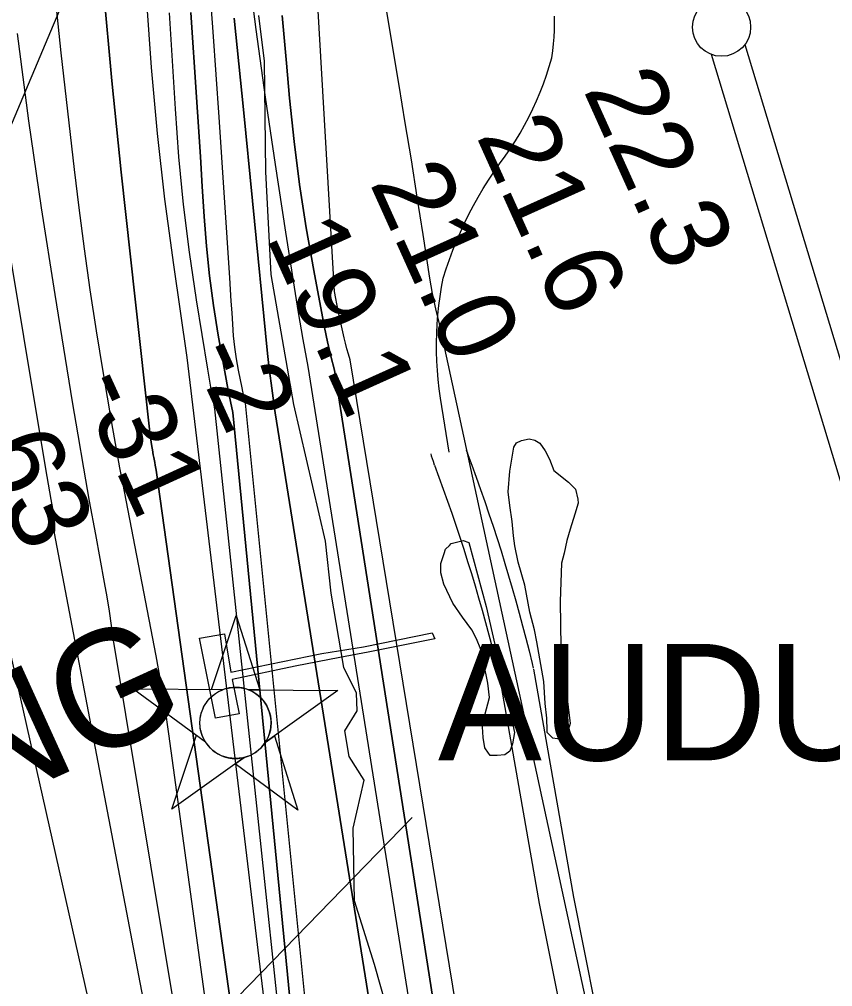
# Model space of a CAD drawing. Extents: x 3651524 to 3689615, y 505651 to 531377.
# Drawn here: x 3660133 to 3660831, y 518426 to 519257 of the extents above; entities that cross this region are included whole.
import ezdxf

# ---------------------------------------------------------------- set-up
doc = ezdxf.new("R2010")
doc.units = 0
for name, color, linetype in [('V-CHAN-DOCK', 7, 'Continuous'), ('V-CHAN-NAID', 7, 'Continuous'), ('V-RIVR-EDGE', 7, 'Continuous'), ('V-RIVR-RANG', 7, 'Continuous'), ('V-ROAD-CNTR', 7, 'Continuous'), ('V-SITE-VEGE', 7, 'Continuous'), ('V-SURV-LINE', 7, 'Continuous'), ('V-TOPO-DPTH', 7, 'Continuous'), ('V-TOPO-MAJR', 7, 'Continuous'), ('V-TOPO-MINR', 7, 'Continuous'), ('V-TOPO-WATR', 7, 'Continuous'), ('V-UTIL-LINE', 7, 'Continuous')]:
    doc.layers.add(name, color=color, linetype=linetype)

msp = doc.modelspace()

# ---------------------------------------------------------------- linework, layer by layer
at = {"layer": 'V-CHAN-DOCK'}
msp.add_lwpolyline([(3660489.731, 518724.865), (3660432.523, 518713.406), (3660408.098, 518709.087), (3660369.958, 518701.446), (3660315.717, 518689.934), (3660321.732, 518660.732), (3660301.475, 518656.933), (3660287.84, 518725.463), (3660309.284, 518729.242), (3660314.644, 518696.488), (3660392.716, 518712.327), (3660428.449, 518718.229), (3660487.452, 518730.249), (3660489.731, 518724.865)], dxfattribs=at)
at = {"layer": 'V-CHAN-NAID'}
for points in [[(3660307.778, 518681.337), (3660298.191, 518681.405), (3660319.317, 518744.889), (3660339.541, 518681.112), (3660329.954, 518681.18), (3660328.377, 518681.758), (3660326.282, 518682.378), (3660324.242, 518682.829), (3660322.206, 518683.137), (3660321.039, 518683.251), (3660319.505, 518683.332), (3660317.783, 518683.33), (3660316.413, 518683.26), (3660314.507, 518683.059), (3660313.141, 518682.84), (3660311.357, 518682.456), (3660309.827, 518682.036), (3660308.795, 518681.705)], [(3660307.778, 518681.337), (3660231.287, 518681.879), (3660292.852, 518636.48), (3660291.739, 518638.389), (3660290.929, 518640.017), (3660290.104, 518641.985), (3660289.408, 518644.039), (3660289.043, 518645.362), (3660288.682, 518646.988), (3660288.438, 518648.433), (3660288.25, 518650.031), (3660288.141, 518651.767), (3660288.129, 518653.348), (3660288.236, 518655.422), (3660288.419, 518657.04), (3660288.811, 518659.243), (3660289.292, 518661.166), (3660289.895, 518663.053), (3660290.55, 518664.732), (3660291.277, 518666.32), (3660292.091, 518667.855), (3660293.152, 518669.592), (3660294.183, 518671.062), (3660295.183, 518672.331), (3660296.185, 518673.477), (3660297.494, 518674.814), (3660298.545, 518675.779), (3660300.262, 518677.176), (3660301.474, 518678.046), (3660303.161, 518679.116), (3660304.892, 518680.061), (3660306.338, 518680.745)], [(3660329.954, 518681.18), (3660406.446, 518680.637), (3660344.243, 518636.115), (3660345.154, 518637.604), (3660346.132, 518639.451), (3660346.847, 518641.036), (3660347.586, 518642.991), (3660348.131, 518644.776), (3660348.529, 518646.415), (3660348.89, 518648.425), (3660349.076, 518649.998), (3660349.2, 518652.204), (3660349.17, 518654.266), (3660348.982, 518656.486), (3660348.716, 518658.244), (3660348.225, 518660.476), (3660347.585, 518662.616), (3660346.835, 518664.598), (3660346.187, 518666.041), (3660345.18, 518667.957), (3660344.118, 518669.679), (3660342.904, 518671.381), (3660341.643, 518672.92), (3660340.371, 518674.286), (3660338.739, 518675.818), (3660336.996, 518677.23), (3660335.313, 518678.407), (3660333.426, 518679.539), (3660331.954, 518680.3)], [(3660326.212, 518623.209), (3660264.009, 518578.687), (3660285.135, 518642.17), (3660292.852, 518636.48), (3660293.487, 518635.516), (3660294.87, 518633.657), (3660296.083, 518632.241), (3660297.549, 518630.738), (3660298.938, 518629.487), (3660300.392, 518628.331), (3660301.795, 518627.344), (3660303.473, 518626.308), (3660305.187, 518625.397), (3660306.978, 518624.586), (3660308.424, 518624.03), (3660310.052, 518623.501), (3660312.278, 518622.937), (3660313.81, 518622.65), (3660315.835, 518622.393), (3660317.372, 518622.289), (3660319.233, 518622.267), (3660320.922, 518622.345), (3660322.632, 518622.521), (3660324.534, 518622.832)], [(3660344.243, 518636.115), (3660352.039, 518641.696), (3660372.263, 518577.919), (3660318.415, 518617.629), (3660326.212, 518623.209), (3660327.878, 518623.685), (3660329.49, 518624.245), (3660331.648, 518625.159), (3660333.383, 518626.043), (3660335.249, 518627.157), (3660336.988, 518628.369), (3660338.54, 518629.614), (3660339.827, 518630.782), (3660341.211, 518632.202), (3660342.415, 518633.604), (3660343.534, 518635.076)]]:
    msp.add_lwpolyline(points, close=True, dxfattribs=at)
msp.add_circle((3660318.664, 518652.802), 30.541, dxfattribs=at)
at = {"layer": 'V-RIVR-EDGE'}
msp.add_lwpolyline([(3660449.43, 518405.026), (3660437.888, 518445.494), (3660420.867, 518500.069), (3660419.796, 518562.57), (3660429.088, 518603.6), (3660416.271, 518623.851), (3660412.649, 518645.919), (3660423.108, 518663.049), (3660422.533, 518678.369), (3660411.558, 518700.454), (3660400.687, 518764.205), (3660395.896, 518808.945), (3660368.613, 518926.044), (3660349.281, 519037.608), (3660344.598, 519125.852), (3660343.607, 519220.827), (3660338.802, 519260.054)], dxfattribs=at)
at = {"layer": 'V-ROAD-CNTR'}
for points in [[(3660501.976, 518885.126), (3660494.673, 518931.668), (3660493.578, 518939.553), (3660492.693, 518947.464), (3660492.021, 518955.396), (3660491.562, 518963.344), (3660491.319, 518971.303), (3660491.288, 518979.263), (3660491.47, 518987.222), (3660491.868, 518995.172), (3660492.476, 519003.11), (3660493.299, 519011.03), (3660494.333, 519018.923), (3660495.581, 519026.785), (3660497.037, 519034.613), (3660499.576, 519042.657), (3660502.321, 519050.636), (3660505.263, 519058.544), (3660508.405, 519066.375), (3660511.745, 519074.123), (3660515.278, 519081.784), (3660519.004, 519089.354), (3660522.919, 519096.827), (3660527.023, 519104.198), (3660531.312, 519111.462), (3660535.783, 519118.613), (3660540.434, 519125.652), (3660545.259, 519132.571), (3660550.258, 519139.364), (3660554.684, 519145.801), (3660558.921, 519152.362), (3660562.964, 519159.047), (3660566.81, 519165.846), (3660570.455, 519172.756), (3660573.896, 519179.771), (3660577.134, 519186.882), (3660580.161, 519194.082), (3660582.975, 519201.371), (3660585.576, 519208.738), (3660587.962, 519216.178), (3660590.126, 519223.684), (3660591.042, 519229.603), (3660591.751, 519235.55), (3660592.252, 519241.518), (3660592.545, 519247.502), (3660592.631, 519253.491), (3660592.508, 519259.479)], [(3660486.267, 518883.729), (3660486.749, 518882.172), (3660488.276, 518877.522), (3660489.339, 518874.431)], [(3660516.738, 518887.006), (3660517.707, 518884.193)], [(3660517.576, 518884.558), (3660521.452, 518874.176), (3660525.27, 518863.714), (3660529.013, 518853.226), (3660532.68, 518842.711), (3660536.27, 518832.17), (3660539.784, 518821.602), (3660543.221, 518811.009), (3660546.58, 518800.392), (3660549.863, 518789.751), (3660553.069, 518779.086), (3660556.197, 518768.399), (3660559.248, 518757.687), (3660562.22, 518746.956), (3660565.115, 518736.204), (3660567.932, 518725.429), (3660570.671, 518714.635), (3660573.327, 518703.837), (3660574.289, 518699.841)], [(3660489.47, 518874.066), (3660493.308, 518863.786), (3660497.052, 518853.53), (3660500.721, 518843.246), (3660504.316, 518832.937), (3660507.836, 518822.6), (3660511.282, 518812.24), (3660514.651, 518801.855), (3660517.946, 518791.444), (3660521.165, 518781.011), (3660524.307, 518770.554), (3660527.375, 518760.075), (3660530.366, 518749.575), (3660533.28, 518739.052), (3660536.119, 518728.51), (3660538.88, 518717.947), (3660541.565, 518707.363), (3660544.177, 518696.745), (3660545.121, 518692.821)], [(3660544.93, 518693.741), (3660579.298, 518497.685), (3660612.46, 518331.561)], [(3660574.48, 518698.921), (3660608.786, 518503.213), (3660636.628, 518363.743)]]:
    msp.add_lwpolyline(points, dxfattribs=at)
at = {"layer": 'V-SITE-VEGE'}
for points in [[(3660557.688, 518889.393), (3660559.91, 518893.129), (3660564.262, 518895.209), (3660570.761, 518896.713), (3660575.594, 518895.547), (3660579.86, 518892.776), (3660584.597, 518886.221), (3660588.246, 518879.147), (3660591.849, 518869.376), (3660604.616, 518859.441), (3660610.443, 518853.408), (3660612.446, 518844.743), (3660612.929, 518841.499), (3660610.062, 518831.842), (3660606.058, 518818.971), (3660603.191, 518809.314), (3660600.844, 518798.568), (3660598.536, 518789.981), (3660597.415, 518757.105), (3660597.798, 518717.73), (3660605.81, 518652.333), (3660604.069, 518645.353), (3660604.03, 518643.199), (3660600.758, 518641.098), (3660596.426, 518640.096), (3660594.79, 518639.048), (3660591.026, 518639.654), (3660586.258, 518644.59), (3660586.286, 518646.207), (3660585.938, 518657), (3660584.54, 518669.428), (3660583.255, 518688.327), (3660577.388, 518722.405), (3660575.412, 518732.686), (3660571.365, 518747.858), (3660566.923, 518771.125), (3660561.336, 518790.639), (3660558.35, 518804.712), (3660557.424, 518813.357), (3660556.025, 518825.786), (3660554.106, 518839.303), (3660552.699, 518851.192), (3660554.092, 518868.964)], [(3660502.271, 518805.167), (3660503.918, 518806.754), (3660514.207, 518809.267), (3660519.03, 518807.565), (3660533.702, 518752.839), (3660550.727, 518678.654), (3660558.215, 518644.547), (3660556.427, 518634.872), (3660554.155, 518628.439), (3660549.785, 518625.281), (3660543.305, 518624.855), (3660537.376, 518624.962), (3660533.157, 518630.43), (3660532.637, 518631.515), (3660531.173, 518640.172), (3660530.796, 518649.345), (3660532.594, 518659.56), (3660536.635, 518674.589), (3660535.238, 518687.018), (3660531.758, 518703.797), (3660529.274, 518715.702), (3660525.66, 518724.937), (3660521.482, 518732.561), (3660513.585, 518743.485), (3660505.167, 518755.499), (3660497.366, 518771.815), (3660494.843, 518781.568), (3660494.987, 518789.653), (3660497.833, 518798.233), (3660498.978, 518801.987)]]:
    msp.add_lwpolyline(points, close=True, dxfattribs=at)
at = {"layer": 'V-SURV-LINE'}
for points in [[(3660756.034, 519235.203), (3660876.692, 518836.198)], [(3660847.983, 518827.494), (3660727.324, 519226.499)]]:
    msp.add_lwpolyline(points, dxfattribs=at)
msp.add_circle((3660735.893, 519249.984), 25, dxfattribs=at)
at = {"layer": 'V-TOPO-DPTH'}
for points in [[(3660205.241, 519282.629), (3660212.412, 519204.024), (3660220.442, 519125.491), (3660244.815, 518904.975), (3660245.253, 518901.266), (3660245.727, 518897.561), (3660246.256, 518893.864), (3660246.821, 518890.171), (3660247.303, 518887.17), (3660248.058, 518882.803), (3660248.477, 518880.628), (3660249.369, 518876.287), (3660249.815, 518874.116), (3660250.687, 518869.77), (3660367.592, 518031.054)], [(3660205.241, 519282.629), (3660212.412, 519204.024), (3660220.442, 519125.491), (3660244.815, 518904.975), (3660245.253, 518901.266), (3660245.727, 518897.561), (3660246.256, 518893.864), (3660246.821, 518890.171), (3660247.303, 518887.17), (3660248.058, 518882.803), (3660248.477, 518880.628), (3660249.369, 518876.287), (3660249.815, 518874.116), (3660250.687, 518869.77), (3660367.592, 518031.054)], [(3660344.498, 518038.702), (3660261.495, 518643.52), (3660258.216, 518665.89), (3660254.475, 518688.188), (3660250.427, 518710.437), (3660221.838, 518858.822), (3660219.404, 518871.676), (3660217.024, 518884.541), (3660214.726, 518897.42), (3660212.483, 518910.309), (3660204.945, 518954.448), (3660199.234, 518989.451), (3660193.87, 519024.506), (3660189.025, 519059.635), (3660184.527, 519094.816), (3660180.549, 519127.872), (3660174.692, 519177.914), (3660169.05, 519227.979), (3660163.731, 519278.08)], [(3660344.498, 518038.702), (3660261.495, 518643.52), (3660258.216, 518665.89), (3660254.475, 518688.188), (3660250.427, 518710.437), (3660221.838, 518858.822), (3660219.404, 518871.676), (3660217.024, 518884.541), (3660214.726, 518897.42), (3660212.483, 518910.309), (3660204.945, 518954.448), (3660199.234, 518989.451), (3660193.87, 519024.506), (3660189.025, 519059.635), (3660184.527, 519094.816), (3660180.549, 519127.872), (3660174.692, 519177.914), (3660169.05, 519227.979), (3660163.731, 519278.08)], [(3660391.13, 518016.01), (3660277.155, 518966.485), (3660265.579, 519046.022), (3660258.116, 519102.367), (3660251.62, 519158.81), (3660246.575, 519215.402), (3660242.497, 519272.092)], [(3660391.13, 518016.01), (3660277.155, 518966.485), (3660265.579, 519046.022), (3660258.116, 519102.367), (3660251.62, 519158.81), (3660246.575, 519215.402), (3660242.497, 519272.092)], [(3660280.448, 519262.481), (3660285.21, 519190.002), (3660286.87, 519164.386), (3660288.5, 519138.768), (3660290.086, 519113.147), (3660291.642, 519087.524), (3660293.628, 519061.954), (3660296.217, 519036.456), (3660299.709, 519011.066), (3660303.803, 518985.748), (3660310.649, 518947.717), (3660312.456, 518938.168), (3660314.378, 518928.643), (3660316.471, 518919.154), (3660403.946, 518019.13)], [(3660403.946, 518019.13), (3660316.471, 518919.154), (3660314.378, 518928.643), (3660312.456, 518938.168), (3660310.649, 518947.717), (3660303.803, 518985.748), (3660299.709, 519011.066), (3660296.217, 519036.456), (3660293.628, 519061.954), (3660291.642, 519087.524), (3660290.086, 519113.147), (3660288.5, 519138.768), (3660286.87, 519164.386), (3660285.21, 519190.002), (3660280.448, 519262.481)], [(3660317.62, 519257.742), (3660325.565, 519179.395), (3660333.363, 519101.034), (3660346.224, 518969.939), (3660347.601, 518957.129), (3660349.136, 518944.339), (3660350.908, 518931.58), (3660352.838, 518918.842), (3660486.821, 518079.665)], [(3660486.821, 518079.665), (3660352.838, 518918.842), (3660350.908, 518931.58), (3660349.136, 518944.339), (3660347.601, 518957.129), (3660346.224, 518969.939), (3660333.363, 519101.034), (3660325.565, 519179.395), (3660317.62, 519257.742)], [(3660358.831, 519259.972), (3660362.302, 519219.012), (3660364.983, 519189.115), (3660368.883, 519151.905), (3660373.527, 519114.8), (3660379.284, 519077.852), (3660385.785, 519041.007), (3660395.145, 518992.252), (3660397.713, 518979.91), (3660400.536, 518967.632), (3660403.738, 518955.446), (3660519.463, 518215.358)]]:
    msp.add_lwpolyline(points, dxfattribs=at)
at = {"layer": 'V-TOPO-MAJR'}
msp.add_lwpolyline([(3660331.859, 518013.486), (3660213.803, 518723.901), (3660212.199, 518736.334), (3660210.434, 518748.743), (3660208.427, 518761.114), (3660206.26, 518773.462), (3660198.621, 518814.619), (3660193.439, 518843.052), (3660188.379, 518871.507), (3660183.504, 518899.993), (3660178.751, 518928.501), (3660163.729, 519020.428), (3660152.119, 519094.993), (3660141.259, 519169.661), (3660131.524, 519244.484)], dxfattribs=at)
at = {"layer": 'V-TOPO-MINR'}
for points in [[(3660417.121, 518964.584), (3660415.625, 518969.239), (3660414.239, 518973.925), (3660413.016, 518978.657), (3660411.904, 518983.418), (3660406.917, 519006.569), (3660403.764, 519022.981), (3660369.467, 519608.342), (3660368.446, 519618.497), (3660367.5, 519628.659), (3660366.667, 519638.83), (3660365.907, 519649.008), (3660360.294, 519730.297), (3660357.146, 519781.141), (3660354.483, 519832.006), (3660352.544, 519882.905), (3660351.089, 519933.825), (3660340.334, 520435.426)], [(3660806.665, 517551.768), (3660493.857, 518995.4), (3660490.531, 519008.344), (3660487.797, 519021.426), (3660485.457, 519034.6), (3660479.674, 519072.1), (3660474.682, 519104.084), (3660469.612, 519136.055), (3660464.424, 519168.007), (3660459.159, 519199.947), (3660387.172, 519631.683)], [(3660418.729, 518011.665), (3660327.319, 518927.2), (3660326.486, 518930.505), (3660325.694, 518933.819), (3660324.964, 518937.147), (3660324.275, 518940.485), (3660321.304, 518955.602), (3660319.583, 518965.391), (3660318.126, 518975.214), (3660317.065, 518985.087), (3660316.267, 518994.994), (3660315.66, 519004.926), (3660315.041, 519014.857), (3660314.405, 519024.787), (3660313.757, 519034.717), (3660304.645, 519172.635), (3660299.521, 519245.905), (3660294.022, 519319.146)], [(3660492.574, 518257.685), (3660381, 518958.662), (3660376.64, 518981.764), (3660372.673, 519004.946), (3660361.741, 519074.131), (3660352.887, 519132.004), (3660344.413, 519189.932), (3660336.509, 519247.939), (3660328.984, 519306.001)], [(3660367.592, 518031.054), (3660250.687, 518869.77), (3660249.815, 518874.116), (3660249.369, 518876.287), (3660248.477, 518880.628), (3660248.058, 518882.803), (3660247.303, 518887.17), (3660246.821, 518890.171), (3660246.256, 518893.864), (3660245.727, 518897.561), (3660245.253, 518901.266), (3660244.815, 518904.975), (3660220.442, 519125.491), (3660212.412, 519204.024), (3660205.241, 519282.629)], [(3660344.498, 518038.702), (3660261.495, 518643.52), (3660258.216, 518665.89), (3660254.475, 518688.188), (3660250.427, 518710.437), (3660221.838, 518858.822), (3660219.404, 518871.676), (3660217.024, 518884.541), (3660214.726, 518897.42), (3660212.483, 518910.309), (3660204.945, 518954.448), (3660199.234, 518989.451), (3660193.87, 519024.506), (3660189.025, 519059.635), (3660184.527, 519094.816), (3660180.549, 519127.872), (3660174.692, 519177.914), (3660169.05, 519227.979), (3660163.731, 519278.08)], [(3660391.13, 518016.01), (3660277.155, 518966.485), (3660265.579, 519046.022), (3660258.116, 519102.367), (3660251.62, 519158.81), (3660246.575, 519215.402), (3660242.497, 519272.092)], [(3660396.337, 518021.601), (3660300.96, 518922.502), (3660297.853, 518939.41), (3660294.941, 518956.356), (3660285.24, 519015.884), (3660279.226, 519056.724), (3660274.05, 519097.656), (3660270.132, 519138.728), (3660267.051, 519179.893), (3660264.564, 519221.126), (3660262.029, 519262.356)], [(3660403.946, 518019.13), (3660316.471, 518919.154), (3660314.378, 518928.643), (3660312.456, 518938.168), (3660310.649, 518947.717), (3660303.803, 518985.748), (3660299.709, 519011.066), (3660296.217, 519036.456), (3660293.628, 519061.954), (3660291.642, 519087.524), (3660290.086, 519113.147), (3660288.5, 519138.768), (3660286.87, 519164.386), (3660285.21, 519190.002), (3660280.448, 519262.481)], [(3660519.463, 518215.358), (3660403.738, 518955.446), (3660400.536, 518967.632), (3660397.713, 518979.91), (3660395.145, 518992.252), (3660385.785, 519041.007), (3660379.284, 519077.852), (3660373.527, 519114.8), (3660368.883, 519151.905), (3660364.983, 519189.115), (3660362.302, 519219.012), (3660358.831, 519259.972)], [(3660324.602, 517969.325), (3660163.361, 518815.805), (3660163.548, 518818.438), (3660163.62, 518821.071), (3660163.517, 518823.702), (3660163.299, 518826.333), (3660162.969, 518828.96), (3660162.606, 518831.582), (3660162.193, 518834.197), (3660161.747, 518836.806), (3660160.323, 518844.698), (3660159.154, 518851.252), (3660158.003, 518857.809), (3660156.878, 518864.37), (3660155.771, 518870.935), (3660098.731, 519213.388)], [(3660544.919, 518184.305), (3660417.121, 518964.584)], [(3660298.206, 517944.122), (3660103.028, 518812.104)]]:
    msp.add_lwpolyline(points, dxfattribs=at)
at = {"layer": 'V-TOPO-WATR'}
msp.add_lwpolyline([(3660486.821, 518079.665), (3660352.838, 518918.842), (3660350.908, 518931.58), (3660349.136, 518944.339), (3660347.601, 518957.129), (3660346.224, 518969.939), (3660333.363, 519101.034), (3660325.565, 519179.395), (3660317.62, 519257.742)], dxfattribs=at)
at = {"layer": 'V-UTIL-LINE'}
for p, q in [((3660309.809, 519601.102), (3658980.81, 516461.163)), ((3658761.746, 516818.972), (3660470.456, 518571.494))]:
    msp.add_line(p, q, dxfattribs=at)

# ---------------------------------------------------------------- texts
at = {"layer": 'V-CHAN-NAID'}
msp.add_text('CITY OF WESTWEGO LANDING ', height=100, rotation=24.453135, dxfattribs=at).set_placement((3658454.716, 517828.486))
msp.add_text('AUDUBON PARK EXCURSION BOAT LANDING (101.7)', height=100, dxfattribs=at).set_placement((3660492.483, 518620.66))
at = {"layer": 'V-RIVR-RANG'}
for s, rotation, p in [('22.3', 294.248326, (3660616.816, 519196.23)), ('21.6', 294.248326, (3660524.98, 519156.625)), ('21.0', 294.248326, (3660433.468, 519116.298)), ('19.1', 294.248326, (3660344.556, 519070.2)), ('-2', 294.528028, (3660279.748, 518969.973)), ('-31', 294.528028, (3660181.99, 518943.323)), ('-63', 294.528028, (3660085.327, 518914.272))]:
    msp.add_text(s, height=67, rotation=rotation, dxfattribs=at).set_placement(p)

doc.saveas('drawing.dxf')
